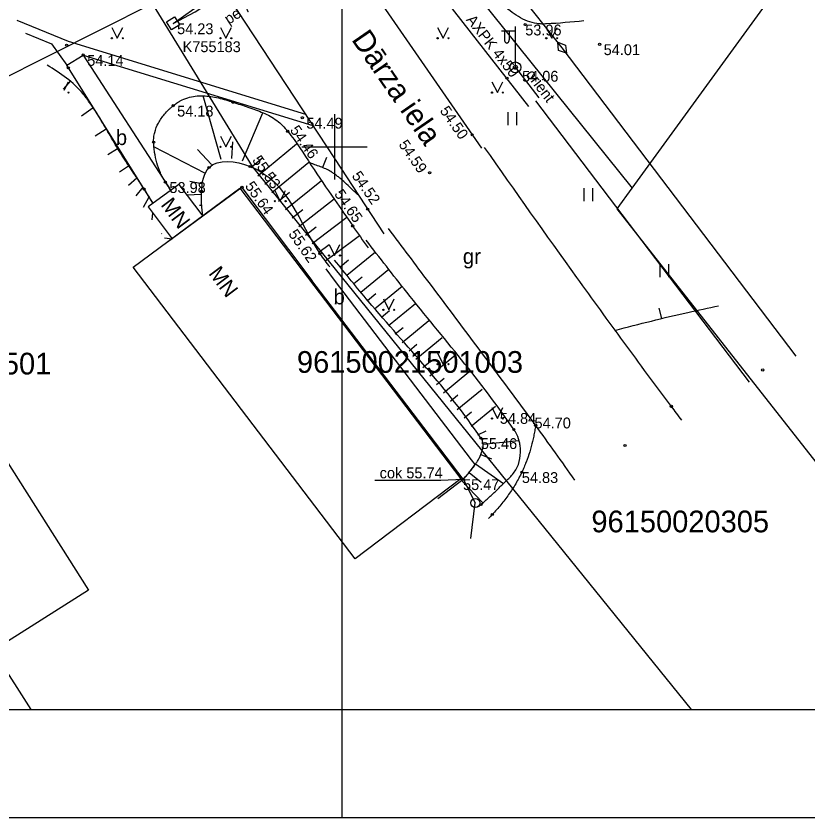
# Model space of a CAD drawing. Extents: x 578395 to 578590, y 418519 to 418816.
# Drawn here: x 578485.34 to 578521.8, y 418519.11 to 418556.02 of the extents above; entities that cross this region are included whole.
import ezdxf

# ---------------------------------------------------------------- set-up
doc = ezdxf.new("R2010")
doc.units = 0
for name, color, linetype in [('APGS_ELEM_####_####_#', 7, 'Continuous'), ('APGS_VADP_ZSPR_####_#', 7, 'Continuous'), ('APGS_VADP_ZSPR_TKST_#', 7, 'Continuous'), ('BUVE_COKL_####_####_#', 7, 'Continuous'), ('BUVE_EKAS_####_####_#', 7, 'Continuous'), ('BUVE_EKAS_RAKS_TKST_#', 7, 'Continuous'), ('BUVE_EKAS_UZMR_####_#', 7, 'Continuous'), ('BUVE_EKAS_UZMR_TKST_#', 7, 'Continuous'), ('CELI_CMAL_####_####_#', 7, 'Continuous'), ('CELI_CSEG_####_TKST_#', 7, 'Continuous'), ('CELI_IELA_####_TKST_#', 7, 'Continuous'), ('CELI_TAKA_####_####_#', 7, 'Continuous'), ('ELEK_ACRL_####_TKST_#', 7, 'Continuous'), ('ELEK_ELEM_####_####_#', 7, 'Continuous'), ('ELEK_ELEM_####_TKST_#', 7, 'Continuous'), ('ELEK_VADP_ZSPR_####_#', 7, 'Continuous'), ('ELEK_VADP_ZSPR_####_I', 7, 'Continuous'), ('ELEK_VADP_ZSPR_TKST_#', 7, 'Continuous'), ('GEOD_ELEM_####_####_#', 7, 'Continuous'), ('NORB_ELEM_####_####_#', 7, 'Continuous'), ('NORB_ZOGS_BARJ_####_#', 7, 'Continuous'), ('NORB_ZOGS_ZSTP_####_#', 7, 'Continuous'), ('RAMI_PLAN_####_TKST_#', 7, 'Continuous'), ('RELJ_AATZ_####_TKST_#', 7, 'Continuous'), ('RELJ_ELEM_####_####_#', 7, 'Continuous'), ('RELJ_HORZ_PAMT_####_#', 7, 'Continuous'), ('RELJ_HORZ_RESN_####_#', 7, 'Continuous'), ('RELJ_NOGA_####_####_#', 7, 'Continuous'), ('RELJ_NOGL_####_####_#', 7, 'Continuous'), ('ROBZ_UZMR_####_####_#', 7, 'Continuous'), ('ROBZ_UZMR_####_TKST_#', 7, 'Continuous'), ('TERT_ELEM_####_####_#', 7, 'Continuous')]:
    doc.layers.add(name, color=color, linetype=linetype)

msp = doc.modelspace()

# ---------------------------------------------------------------- linework, layer by layer
at = {"layer": 'APGS_ELEM_####_####_#'}
for p, q in [((578508.331, 418553.66), (578508.331, 418555.543)), ((578508.331, 418555.327), (578507.696, 418555.322)), ((578507.831, 418555.323), (578507.831, 418554.931)), ((578508.041, 418555.325), (578508.041, 418554.931))]:
    msp.add_line(p, q, dxfattribs=at)
for radius in [0.25, 0.09, 0.0225]:
    msp.add_circle((578508.331, 418553.66), radius, dxfattribs=at)
msp.add_ellipse((578507.936, 418554.931), major_axis=(0, 0.151), ratio=0.695971, start_param=1.570796, end_param=4.712389, dxfattribs=at)
at = {"layer": 'APGS_VADP_ZSPR_####_#'}
for points in [[(578508.331, 418553.66), (578509.403, 418552.257)], [(578509.258, 418552.12), (578519.096, 418539.163)]]:
    msp.add_lwpolyline(points, dxfattribs=at)
at = {"layer": 'BUVE_COKL_####_####_#'}
for p, q in [((578501.853, 418534.667), (578504.893, 418534.667)), ((578504.893, 418534.667), (578505.919, 418534.705))]:
    msp.add_line(p, q, dxfattribs=at)
at = {"layer": 'BUVE_EKAS_####_####_#'}
for p, q in [((578492.835, 418548.272), (578491.424, 418547.236)), ((578495.74, 418548.137), (578492.304, 418545.615)), ((578492.835, 418548.272), (578493.932, 418546.81)), ((578495.74, 418548.137), (578498.956, 418543.852)), ((578491.424, 418547.236), (578492.521, 418545.774)), ((578500, 418542.489), (578498.96, 418543.856)), ((578505.919, 418534.705), (578500, 418542.489)), ((578504.752, 418533.818), (578505.919, 418534.705))]:
    msp.add_line(p, q, dxfattribs=at)
at = {"layer": 'BUVE_EKAS_UZMR_####_#'}
for p, q in [((578490.73, 418544.46), (578495.64, 418548.1)), ((578495.64, 418548.1), (578505.81, 418534.72)), ((578500.95, 418531.04), (578490.73, 418544.46)), ((578484.55, 418536.09), (578488.67, 418529.6)), ((578505.81, 418534.72), (578500.95, 418531.04)), ((578488.67, 418529.6), (578484.283, 418526.815)), ((578484.283, 418526.815), (578486.01, 418524.111))]:
    msp.add_line(p, q, dxfattribs=at)
at = {"layer": 'CELI_CMAL_####_####_#'}
for points in [[(578489.611, 418565.18), (578494.048, 418558.537), (578500, 418549.461)], [(578500, 418559.737), (578506.766, 418549.939)], [(578487.671, 418553.755), (578488.429, 418554.229)], [(578488.429, 418554.229), (578492.459, 418547.996)], [(578491.649, 418547.401), (578487.671, 418553.755)], [(578500, 418549.461), (578502.276, 418545.991)], [(578500, 418543.868), (578499.609, 418544.381)], [(578505.919, 418534.705), (578506.196, 418535.005), (578506.475, 418535.375), (578506.313, 418535.595), (578500, 418543.868)]]:
    msp.add_lwpolyline(points, dxfattribs=at)
for points in [[(578515.994, 418537.424), (578515.513, 418538.058), (578513.326, 418541.011), (578511.166, 418543.983), (578506.911, 418549.972)], [(578511.068, 418534.662), (578509.263, 418537.183), (578506.821, 418540.479), (578504.353, 418543.758), (578502.492, 418546.237)]]:
    msp.add_spline(points, degree=3, dxfattribs=at)
at = {"layer": 'CELI_TAKA_####_####_#'}
msp.add_line((578488.429, 418554.229), (578499.002, 418550.982), dxfattribs=at)
for points in [[(578485.37, 418555.828), (578487.731, 418554.869), (578498.659, 418551.506)], [(578485.774, 418555.232), (578486.963, 418554.749), (578487.671, 418553.755)]]:
    msp.add_lwpolyline(points, dxfattribs=at)
msp.add_spline([(578509.263, 418537.183), (578509.219, 418536.935), (578509.172, 418536.69), (578509.118, 418536.447), (578508.988, 418535.967), (578508.825, 418535.494), (578508.731, 418535.26), (578508.68, 418535.144), (578508.626, 418535.029), (578508.49, 418534.759), (578508.343, 418534.497), (578508.019, 418533.997), (578507.658, 418533.526), (578507.465, 418533.301), (578507.264, 418533.082), (578507.091, 418532.899)], degree=3, dxfattribs=at)
at = {"layer": 'ELEK_ELEM_####_####_#'}
for points in [[(578492.637, 418555.993), (578492.871, 418555.612), (578492.497, 418555.381), (578492.263, 418555.762)], [(578510.285, 418554.817), (578510.639, 418554.685), (578510.675, 418554.309), (578510.321, 418554.441)]]:
    msp.add_lwpolyline(points, close=True, dxfattribs=at)
at = {"layer": 'ELEK_VADP_ZSPR_####_#'}
for points in [[(578521.251, 418540.371), (578510.48, 418554.563), (578505.094, 418561.359), (578500, 418572.157)], [(578508.955, 418551.863), (578504.881, 418557.075), (578502.948, 418560.316), (578502.614, 418561.156)]]:
    msp.add_lwpolyline(points, dxfattribs=at)
at = {"layer": 'ELEK_VADP_ZSPR_####_I'}
for points in [[(578492.567, 418555.687), (578493.524, 418556.347), (578500, 418560.526)], [(578492.567, 418555.687), (578493.577, 418556.224), (578500, 418560.387)]]:
    msp.add_lwpolyline(points, dxfattribs=at)
at = {"layer": 'GEOD_ELEM_####_####_#'}
for p, q in [((578500, 418551.5), (578500, 418550)), ((578498.5, 418550), (578500, 418550)), ((578500, 418550), (578500, 418548.5)), ((578500, 418550), (578501.5, 418550))]:
    msp.add_line(p, q, dxfattribs=at)
at = {"layer": 'NORB_ELEM_####_####_#'}
msp.add_circle((578506.483, 418533.61), 0.202, dxfattribs=at)
at = {"layer": 'NORB_ZOGS_BARJ_####_#'}
msp.add_lwpolyline([(578506.283, 418531.98), (578506.483, 418533.61)], dxfattribs=at)
at = {"layer": 'NORB_ZOGS_ZSTP_####_#'}
msp.add_lwpolyline([(578505.919, 418534.705), (578506.483, 418533.61)], dxfattribs=at)
at = {"layer": 'RAMI_PLAN_####_TKST_#'}
for p, q in [((578500.351, 418519.111), (578500.351, 418667.611)), ((578590.351, 418519.111), (578395.351, 418519.111))]:
    msp.add_line(p, q, dxfattribs=at)
msp.add_lwpolyline([(578410.351, 418811.111), (578410.351, 418524.111), (578585.351, 418524.111), (578585.351, 418811.111)], close=True, dxfattribs=at)
at = {"layer": 'RELJ_ELEM_####_####_#'}
for centre in [(578508.782, 418555.63), (578487.664, 418554.68), (578512.208, 418554.723), (578488.429, 418554.229), (578487.743, 418553.64), (578507.939, 418553.163), (578492.569, 418551.894), (578495.327, 418552.055), (578498.516, 418551.341), (578497.846, 418550.717), (578491.671, 418550.217), (578506.34, 418550.555), (578494.223, 418549.051), (578496.113, 418549.1), (578504.382, 418548.809), (578492.212, 418548.378), (578491.238, 418548.057), (578495.74, 418548.137), (578493.874, 418547.951), (578501.525, 418547.136), (578500.84, 418546.362), (578499.327, 418545.081), (578519.719, 418539.732), (578515.513, 418538.058), (578508.255, 418536.99), (578509.263, 418537.183), (578506.738, 418536.593), (578513.379, 418536.253), (578508.626, 418535.029), (578505.919, 418534.705), (578506.745, 418533.538), (578507.264, 418533.082)]:
    msp.add_circle(centre, 0.05, dxfattribs=at)
at = {"layer": 'RELJ_HORZ_PAMT_####_#'}
for p, q in [((578499.634, 418549.513), (578499.451, 418549.048)), ((578514.94, 418542.579), (578515.06, 418542.094))]:
    msp.add_line(p, q, dxfattribs=at)
for points in [[(578500, 418548.753), (578499.918, 418548.81), (578499.876, 418548.837), (578499.855, 418548.85), (578499.844, 418548.857), (578499.839, 418548.86), (578499.834, 418548.863), (578499.599, 418548.986), (578499.35, 418549.086), (578499.095, 418549.178), (578498.969, 418549.225), (578498.844, 418549.274)], [(578501.101, 418547.783), (578500.963, 418547.904), (578500.827, 418548.029), (578500.559, 418548.282), (578500.286, 418548.528), (578500.145, 418548.644), (578500, 418548.753)], [(578512.912, 418541.556), (578516.273, 418542.384), (578517.688, 418542.684)]]:
    msp.add_spline(points, degree=3, dxfattribs=at)
at = {"layer": 'RELJ_HORZ_RESN_####_#'}
msp.add_spline([(578511.475, 418555.796), (578509.769, 418555.66), (578509.541, 418555.655), (578509.319, 418555.678), (578508.888, 418555.794), (578508.084, 418556.26), (578507.35, 418556.933), (578507.008, 418557.307), (578506.682, 418557.685), (578506.133, 418558.351), (578505.615, 418559.017), (578504.68, 418560.369), (578503.885, 418561.771), (578503.544, 418562.502), (578503.241, 418563.256), (578502.051, 418566.491)], degree=3, dxfattribs=at)
at = {"layer": 'RELJ_NOGA_####_####_#'}
for p, q in [((578487.527, 418552.65), (578487.864, 418553.039)), ((578494.781, 418549.418), (578493.956, 418552.349)), ((578488.358, 418551.426), (578488.882, 418551.813)), ((578495.761, 418549.353), (578496.699, 418551.574)), ((578488.983, 418550.506), (578489.484, 418550.836)), ((578489.566, 418549.648), (578490.013, 418549.93)), ((578494.058, 418548.778), (578491.685, 418549.995)), ((578495.276, 418549.466), (578495.324, 418550.232)), ((578496.473, 418548.668), (578498.246, 418550.143)), ((578494.343, 418549.186), (578493.695, 418549.885)), ((578496.153, 418549.052), (578496.694, 418549.504)), ((578497.11, 418547.897), (578498.824, 418549.303)), ((578490.102, 418548.858), (578490.521, 418549.135)), ((578490.52, 418548.242), (578490.904, 418548.569)), ((578496.792, 418548.283), (578497.315, 418548.715)), ((578497.741, 418547.121), (578499.401, 418548.46)), ((578490.86, 418547.741), (578491.183, 418548.144)), ((578493.897, 418548.307), (578493.346, 418548.408)), ((578491.21, 418547.225), (578491.46, 418547.702)), ((578493.881, 418547.809), (578493.208, 418547.775)), ((578497.426, 418547.509), (578497.932, 418547.921)), ((578498.363, 418546.338), (578499.982, 418547.609)), ((578491.602, 418546.648), (578491.633, 418546.957)), ((578493.906, 418547.309), (578493.784, 418547.303)), ((578498.053, 418546.73), (578498.545, 418547.121)), ((578493.932, 418546.81), (578493.931, 418546.81)), ((578500, 418546.33), (578500.565, 418546.76)), ((578498.67, 418545.944), (578499.151, 418546.316)), ((578498.975, 418545.547), (578500, 418546.33)), ((578492.041, 418546.002), (578492.043, 418546.015)), ((578500, 418545.065), (578501.146, 418545.92)), ((578492.17, 418545.811), (578492.521, 418545.774)), ((578492.488, 418545.778), (578492.488, 418545.777)), ((578492.521, 418545.774), (578492.521, 418545.775)), ((578499.276, 418545.148), (578499.751, 418545.504)), ((578500.575, 418544.092), (578501.881, 418545.165)), ((578499.576, 418544.748), (578500, 418545.065)), ((578500.257, 418544.478), (578500.652, 418544.802)), ((578501.21, 418543.319), (578502.496, 418544.376)), ((578500.892, 418543.705), (578501.281, 418544.025)), ((578501.845, 418542.546), (578503.111, 418543.587)), ((578501.527, 418542.933), (578501.91, 418543.247)), ((578502.48, 418541.774), (578503.726, 418542.798)), ((578502.162, 418542.16), (578502.539, 418542.47)), ((578503.115, 418541.001), (578504.341, 418542.01)), ((578502.797, 418541.388), (578503.168, 418541.693)), ((578503.75, 418540.229), (578504.956, 418541.221)), ((578503.432, 418540.615), (578503.797, 418540.915)), ((578504.385, 418539.456), (578505.571, 418540.432)), ((578504.067, 418539.843), (578504.426, 418540.138)), ((578505.02, 418538.684), (578506.187, 418539.643)), ((578504.702, 418539.07), (578505.055, 418539.36)), ((578505.655, 418537.911), (578506.802, 418538.854)), ((578505.337, 418538.297), (578505.684, 418538.583)), ((578505.972, 418537.525), (578506.313, 418537.805)), ((578506.29, 418537.139), (578507.417, 418538.065)), ((578506.607, 418536.752), (578506.976, 418536.936)), ((578506.843, 418536.324), (578508.497, 418536.49)), ((578506.742, 418535.839), (578507.233, 418535.64)), ((578506.497, 418535.405), (578507.787, 418534.51)), ((578506.196, 418535.005), (578506.746, 418534.561)), ((578505.853, 418534.643), (578506.826, 418533.61))]:
    msp.add_line(p, q, dxfattribs=at)
for points in [[(578493.932, 418546.81), (578493.874, 418547.951), (578494.223, 418549.051), (578496.113, 418549.1), (578499.327, 418545.081), (578499.782, 418544.472)], [(578505.853, 418534.643), (578505.919, 418534.705), (578506.077, 418534.866), (578506.223, 418535.038), (578506.361, 418535.218), (578506.496, 418535.404), (578506.586, 418535.539), (578506.671, 418535.688), (578506.803, 418536.008), (578506.846, 418536.237), (578506.84, 418536.354), (578506.811, 418536.466), (578506.738, 418536.593), (578501.557, 418542.896), (578500, 418544.791)]]:
    msp.add_spline(points, degree=3, dxfattribs=at)
at = {"layer": 'RELJ_NOGL_####_####_#'}
for points in [[(578491.649, 418547.401), (578491.238, 418548.057), (578490.816, 418548.7), (578490.6, 418549.018), (578490.385, 418549.337), (578489.906, 418550.109), (578489.453, 418550.89), (578488.975, 418551.672), (578488.711, 418552.062), (578488.57, 418552.256), (578488.422, 418552.449), (578486.773, 418553.761)], [(578492.459, 418547.996), (578492.212, 418548.378), (578492.09, 418548.586), (578491.984, 418548.806), (578491.819, 418549.271), (578491.715, 418549.749), (578491.686, 418549.986), (578491.677, 418550.102), (578491.671, 418550.217), (578491.68, 418550.442), (578491.72, 418550.664), (578491.892, 418551.097), (578492.177, 418551.509), (578492.361, 418551.705), (578492.462, 418551.801), (578492.569, 418551.894), (578492.732, 418552.017), (578492.898, 418552.118), (578493.241, 418552.261), (578493.949, 418552.35), (578494.656, 418552.251), (578494.999, 418552.159), (578495.327, 418552.055), (578496.015, 418551.831), (578496.712, 418551.569), (578497.346, 418551.215), (578497.846, 418550.717), (578498.928, 418549.151), (578500, 418547.583)], [(578500, 418547.583), (578500.84, 418546.362), (578501.543, 418545.348)], [(578506.631, 418533.437), (578506.745, 418533.538), (578507.118, 418533.874), (578507.485, 418534.216), (578507.844, 418534.567), (578508.197, 418534.927), (578508.354, 418535.137), (578508.467, 418535.384), (578508.564, 418535.943), (578508.557, 418536.15), (578508.529, 418536.356), (578508.394, 418536.766), (578508.255, 418536.99), (578503.325, 418543.313), (578501.464, 418545.699)]]:
    msp.add_spline(points, degree=3, dxfattribs=at)
at = {"layer": 'ROBZ_UZMR_####_####_#'}
for p, q in [((578513.707, 418548.097), (578533.748, 418575.711)), ((578440.85, 418531.07), (578491.621, 418556.597)), ((578496.218, 418549.102), (578491.621, 418556.597)), ((578506.631, 418556.899), (578513.707, 418548.097)), ((578516.431, 418524.111), (578496.218, 418549.102)), ((578513.014, 418547.143), (578513.707, 418548.097)), ((578522.351, 418535.28), (578513.014, 418547.143))]:
    msp.add_line(p, q, dxfattribs=at)
at = {"layer": 'TERT_ELEM_####_####_#'}
for p, q in [((578489.75, 418555.5), (578490, 418555)), ((578490, 418555), (578490.25, 418555.5)), ((578494.75, 418555.5), (578495, 418555)), ((578495, 418555), (578495.25, 418555.5)), ((578504.75, 418555.5), (578505, 418555)), ((578505, 418555), (578505.25, 418555.5)), ((578509.75, 418555.5), (578510, 418555)), ((578510, 418555), (578510.25, 418555.5)), ((578487.555, 418552.61), (578487.75, 418553)), ((578507.25, 418553), (578507.5, 418552.5)), ((578507.5, 418552.5), (578507.75, 418553)), ((578508, 418551), (578508, 418551.6)), ((578508.4, 418551), (578508.4, 418551.6)), ((578494.75, 418550.5), (578495, 418550)), ((578495, 418550), (578495.25, 418550.5)), ((578511.5, 418547.5), (578511.5, 418548.1)), ((578511.9, 418547.5), (578511.9, 418548.1)), ((578497.25, 418548), (578497.5, 418547.5)), ((578497.5, 418547.5), (578497.75, 418548)), ((578499.75, 418545.5), (578500, 418545)), ((578500, 418545), (578500.25, 418545.5)), ((578515, 418544), (578515, 418544.6)), ((578515.4, 418544), (578515.4, 418544.6)), ((578502.25, 418543), (578502.5, 418542.5)), ((578502.5, 418542.5), (578502.75, 418543)), ((578504.75, 418540.5), (578505, 418540)), ((578505, 418540), (578505.25, 418540.5)), ((578507.25, 418538), (578507.5, 418537.5)), ((578507.5, 418537.5), (578507.75, 418538))]:
    msp.add_line(p, q, dxfattribs=at)
for centre, radius in [((578489.75, 418555), 0.028), ((578490.25, 418555), 0.0263), ((578494.75, 418555), 0.028), ((578495.25, 418555), 0.0263), ((578504.75, 418555), 0.028), ((578505.25, 418555), 0.0263), ((578509.75, 418555), 0.028), ((578510.25, 418555), 0.0263), ((578487.75, 418552.5), 0.0263), ((578507.25, 418552.5), 0.028), ((578507.75, 418552.5), 0.0263), ((578494.75, 418550), 0.028), ((578495.25, 418550), 0.0263), ((578497.25, 418547.5), 0.028), ((578497.75, 418547.5), 0.0263), ((578499.75, 418545), 0.028), ((578500.25, 418545), 0.0263), ((578502.25, 418542.5), 0.028), ((578502.75, 418542.5), 0.0263), ((578504.75, 418540), 0.028), ((578505.25, 418540), 0.0263), ((578507.25, 418537.5), 0.028), ((578507.75, 418537.5), 0.0263)]:
    msp.add_circle(centre, radius, dxfattribs=at)

# ---------------------------------------------------------------- texts
at = {"layer": 'APGS_VADP_ZSPR_TKST_#'}
msp.add_text('orient', height=0.5, rotation=307.3978, dxfattribs=at).set_placement((578508.778, 418553.33))
at = {"layer": 'BUVE_COKL_####_####_#'}
msp.add_text('cok 55.74', height=0.5, dxfattribs=at).set_placement((578502.081, 418534.743))
at = {"layer": 'BUVE_EKAS_RAKS_TKST_#'}
for p in [(578491.971, 418547.329), (578494.174, 418544.17)]:
    msp.add_text('MN', height=0.7, rotation=306.891, dxfattribs=at).set_placement(p)
at = {"layer": 'BUVE_EKAS_UZMR_TKST_#'}
msp.add_text('96150021501003', height=1, dxfattribs=at).set_placement((578498.27, 418539.6))
at = {"layer": 'CELI_CSEG_####_TKST_#'}
for s, p in [('b', (578489.93, 418550.085)), ('gr', (578505.91, 418544.614)), ('b', (578499.953, 418542.752))]:
    msp.add_text(s, height=0.7, dxfattribs=at).set_placement(p)
at = {"layer": 'CELI_IELA_####_TKST_#'}
msp.add_text('Dārza iela', height=1, rotation=304.6234, dxfattribs=at).set_placement((578500.754, 418554.941))
at = {"layer": 'ELEK_ACRL_####_TKST_#'}
msp.add_text('pe 750N d110', height=0.5, rotation=32.9519, dxfattribs=at).set_placement((578495.128, 418555.619))
at = {"layer": 'ELEK_ELEM_####_TKST_#'}
msp.add_text('K755183', height=0.5, dxfattribs=at).set_placement((578493.007, 418554.36))
at = {"layer": 'ELEK_VADP_ZSPR_TKST_#'}
msp.add_text('AXPK 4x50', height=0.5, rotation=308.0146, dxfattribs=at).set_placement((578506.036, 418555.841))
at = {"layer": 'RELJ_AATZ_####_TKST_#'}
for s, p in [(' 54.23', (578492.567, 418555.187)), ('53.96', (578508.782, 418555.13)), (' 54.01', (578512.208, 418554.223)), (' 54.14', (578488.429, 418553.729)), (' 54.06', (578508.451, 418553)), (' 54.18', (578492.569, 418551.394)), (' 54.49', (578498.516, 418550.841)), (' 53.98', (578492.212, 418547.878)), ('54.84', (578507.614, 418537.252)), ('54.70', (578509.209, 418537.042)), ('55.46', (578506.738, 418536.093)), ('54.83', (578508.626, 418534.529)), ('55.47', (578505.919, 418534.205))]:
    msp.add_text(s, height=0.5, dxfattribs=at).set_placement(p)
for s, p in [(' 54.50', (578504.721, 418551.815)), (' 54.46', (578497.819, 418550.922)), (' 54.59', (578502.823, 418550.258)), (' 55.53', (578496.082, 418549.54)), (' 54.52', (578500.666, 418548.819)), (' 55.64', (578495.749, 418548.349)), (' 54.65', (578499.858, 418547.982)), (' 55.62', (578497.75, 418546.141))]:
    msp.add_text(s, height=0.5, rotation=305, dxfattribs=at).set_placement(p)
at = {"layer": 'ROBZ_UZMR_####_TKST_#'}
for s, p in [('96150021501', (578478.779, 418539.524)), ('96150020305', (578511.83, 418532.259))]:
    msp.add_text(s, height=1, dxfattribs=at).set_placement(p)

doc.saveas('drawing.dxf')
